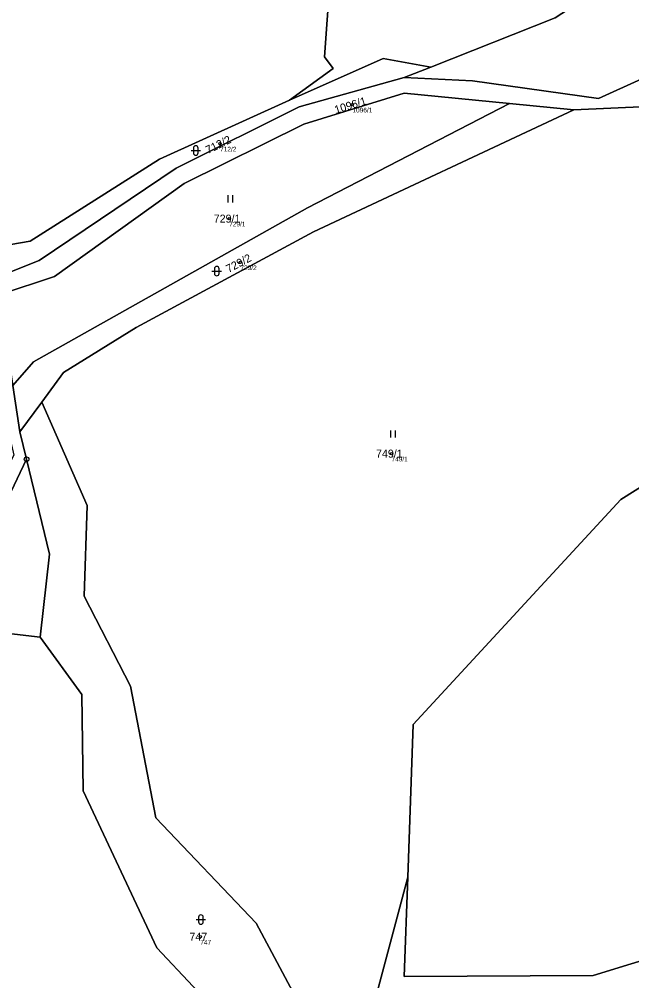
# Model space of a CAD drawing. Extents: x -554500 to -548272, y -1079733 to -1073730.
# Drawn here: x -552674.2 to -552544.1, y -1076720.4 to -1076516.2 of the extents above; entities that cross this region are included whole.
import ezdxf

# ---------------------------------------------------------------- set-up
doc = ezdxf.new("R2010")
doc.units = 0
for name, color, linetype in [('Definiční body', 7, 'Continuous'), ('Hranice parcel', 7, 'Continuous'), ('Parcelní čísla', 7, 'Continuous'), ('Polygon parcely', 7, 'Continuous'), ('Značky bodu BP', 7, 'Continuous'), ('Značky kultur', 7, 'Continuous')]:
    doc.layers.add(name, color=color, linetype=linetype)

msp = doc.modelspace()

# ---------------------------------------------------------------- linework, layer by layer
at = {"layer": 'Definiční body'}
for centre in [(-552603.42, -1076534.33994), (-552631.54, -1076542.62994), (-552629.61, -1076558.53994), (-552627.22, -1076567.79994), (-552595.12, -1076608.42994), (-552635.75, -1076711.01994)]:
    msp.add_circle(centre, 0.25, dxfattribs=at)
at = {"layer": 'Hranice parcel'}
for p, q in [((-552592.41, -1076528.61), (-552586.77, -1076526.37)), ((-552556.35, -1076535.43), (-552570.04, -1076534.1)), ((-552675.63, -1076593.95), (-552674.1, -1076603.82)), ((-552674.1, -1076603.82), (-552669.45, -1076597.48)), ((-552674.1, -1076603.82), (-552672.69, -1076609.64)), ((-552669.8, -1076647.4), (-552694.57, -1076644.52))]:
    msp.add_line(p, q, dxfattribs=at)
for points in [[(-552616.83, -1076533.42), (-552607.55, -1076526.7), (-552609.35, -1076524.22), (-552607.13, -1076493.71), (-552602.77, -1076462.46), (-552606.68, -1076454.87), (-552601.23, -1076431.08)], [(-552586.77, -1076526.37), (-552560.32, -1076515.93), (-552515.35, -1076486.6)], [(-552592.41, -1076528.61), (-552577.9, -1076529.28), (-552551.15, -1076533.06), (-552541.94, -1076528.83), (-552523.76, -1076530.08), (-552497.9, -1076522.82), (-552486.35, -1076519.2)], [(-552586.77, -1076526.37), (-552596.9, -1076524.56), (-552616.83, -1076533.42)], [(-552487.5, -1076524.06), (-552494.64, -1076526.4), (-552523.34, -1076533.93), (-552556.35, -1076535.43)], [(-552680.53, -1076571.59), (-552670.01, -1076567.43), (-552640.86, -1076547.83), (-552614.73, -1076534.83), (-552592.41, -1076528.61)], [(-552681.83, -1076565.04), (-552671.92, -1076563.36), (-552644.44, -1076545.91), (-552616.83, -1076533.42)], [(-552570.04, -1076534.1), (-552592.41, -1076531.92), (-552613.77, -1076538.47), (-552639.17, -1076551.08), (-552666.75, -1076570.81), (-552678.36, -1076574.64), (-552677.68, -1076580.73), (-552675.63, -1076593.95)], [(-552675.63, -1076593.95), (-552671.17, -1076588.94), (-552612.98, -1076556.28), (-552570.04, -1076534.1)], [(-552669.45, -1076597.48), (-552664.86, -1076591.22), (-552649.36, -1076581.64), (-552611.72, -1076561.31), (-552556.35, -1076535.43)], [(-552591.68, -1076698.35), (-552590.54, -1076665.97), (-552546.35, -1076618.16), (-552480.18, -1076576.63)], [(-552606.96, -1076782.38), (-552614.61, -1076740.01), (-552614.42, -1076725.85), (-552623.86, -1076708.12), (-552645.2, -1076685.73), (-552650.59, -1076657.78), (-552660.44, -1076638.73), (-552659.8, -1076619.44), (-552669.45, -1076597.48)], [(-552672.69, -1076609.64), (-552678.7, -1076622.12), (-552694.57, -1076644.52)], [(-552669.8, -1076647.4), (-552667.82, -1076629.78), (-552672.69, -1076609.64)], [(-552618.04, -1076776.84), (-552620.31, -1076767.74), (-552628.49, -1076753.02), (-552630.07, -1076741.43), (-552629.55, -1076729.8), (-552644.98, -1076713.39), (-552660.65, -1076680.06), (-552660.92, -1076659.58), (-552669.8, -1076647.4)], [(-552606.96, -1076782.38), (-552603.83, -1076744), (-552591.68, -1076698.35)], [(-552487.68, -1076699.44), (-552552.28, -1076719.26), (-552592.42, -1076719.43), (-552591.68, -1076698.35)]]:
    msp.add_lwpolyline(points, dxfattribs=at)
at = {"layer": 'Polygon parcely'}
for points in [[(-552518.46, -1076483.85), (-552483.61, -1076456.09), (-552448.47, -1076430.54), (-552457.53, -1076406.36), (-552525.71, -1076388.4), (-552593.59, -1076427.89), (-552601.23, -1076431.08), (-552606.68, -1076454.87), (-552602.77, -1076462.46), (-552607.13, -1076493.71), (-552609.35, -1076524.22), (-552607.55, -1076526.7), (-552616.83, -1076533.42), (-552596.9, -1076524.56), (-552586.77, -1076526.37), (-552560.32, -1076515.93), (-552515.35, -1076486.6)], [(-552671.92, -1076563.36), (-552644.44, -1076545.91), (-552616.83, -1076533.42), (-552607.55, -1076526.7), (-552609.35, -1076524.22), (-552607.13, -1076493.71), (-552602.77, -1076462.46), (-552606.68, -1076454.87), (-552601.23, -1076431.08), (-552610.94, -1076435.25), (-552618.03, -1076437.64), (-552701.4, -1076465.61), (-552701.24, -1076466.42), (-552698.36, -1076481.06), (-552684.08, -1076553.72), (-552681.41, -1076548.9), (-552679.88, -1076552.32), (-552683.15, -1076558.42), (-552681.83, -1076565.04)], [(-552497.9, -1076522.82), (-552486.35, -1076519.2), (-552480.24, -1076488.14), (-552495.5, -1076499.17), (-552515.35, -1076486.6), (-552560.32, -1076515.93), (-552586.77, -1076526.37), (-552592.41, -1076528.61), (-552577.9, -1076529.28), (-552551.15, -1076533.06), (-552541.94, -1076528.83), (-552523.76, -1076530.08)], [(-552670.01, -1076567.43), (-552640.86, -1076547.83), (-552614.73, -1076534.83), (-552592.41, -1076528.61), (-552586.77, -1076526.37), (-552596.9, -1076524.56), (-552616.83, -1076533.42), (-552644.44, -1076545.91), (-552671.92, -1076563.36), (-552681.83, -1076565.04), (-552680.53, -1076571.59)], [(-552487.5, -1076524.06), (-552494.64, -1076526.4), (-552523.34, -1076533.93), (-552556.35, -1076535.43), (-552611.72, -1076561.31), (-552649.36, -1076581.64), (-552664.86, -1076591.22), (-552669.45, -1076597.48), (-552659.8, -1076619.44), (-552660.44, -1076638.73), (-552650.59, -1076657.78), (-552645.2, -1076685.73), (-552623.86, -1076708.12), (-552614.42, -1076725.85), (-552614.61, -1076740.01), (-552606.96, -1076782.38), (-552603.83, -1076744), (-552591.68, -1076698.35), (-552590.54, -1076665.97), (-552546.35, -1076618.16), (-552480.18, -1076576.63), (-552490.19, -1076536.01)], [(-552666.75, -1076570.81), (-552678.36, -1076574.64), (-552677.68, -1076580.73), (-552675.63, -1076593.95), (-552671.17, -1076588.94), (-552612.98, -1076556.28), (-552570.04, -1076534.1), (-552592.41, -1076531.92), (-552613.77, -1076538.47), (-552639.17, -1076551.08)], [(-552570.04, -1076534.1), (-552612.98, -1076556.28), (-552671.17, -1076588.94), (-552675.63, -1076593.95), (-552674.1, -1076603.82), (-552669.45, -1076597.48), (-552664.86, -1076591.22), (-552649.36, -1076581.64), (-552611.72, -1076561.31), (-552556.35, -1076535.43)], [(-552442.82, -1076662.41), (-552388.41, -1076604.22), (-552360.56, -1076591.81), (-552353.27, -1076582.68), (-552346, -1076567.97), (-552349.96, -1076565.5), (-552371.43, -1076578.9), (-552438.38, -1076618.51), (-552465.61, -1076566.07), (-552480.18, -1076576.63), (-552546.35, -1076618.16), (-552590.54, -1076665.97), (-552591.68, -1076698.35), (-552592.42, -1076719.43), (-552552.28, -1076719.26), (-552487.68, -1076699.44)], [(-552672.69, -1076609.64), (-552667.82, -1076629.78), (-552669.8, -1076647.4), (-552660.92, -1076659.58), (-552660.65, -1076680.06), (-552644.98, -1076713.39), (-552629.55, -1076729.8), (-552630.07, -1076741.43), (-552628.49, -1076753.02), (-552620.31, -1076767.74), (-552618.04, -1076776.84), (-552615.91, -1076785.32), (-552606.96, -1076782.38), (-552614.61, -1076740.01), (-552614.42, -1076725.85), (-552623.86, -1076708.12), (-552645.2, -1076685.73), (-552650.59, -1076657.78), (-552660.44, -1076638.73), (-552659.8, -1076619.44), (-552669.45, -1076597.48), (-552674.1, -1076603.82)], [(-552678.7, -1076622.12), (-552694.57, -1076644.52), (-552669.8, -1076647.4), (-552667.82, -1076629.78), (-552672.69, -1076609.64)], [(-552720.84, -1076681.61), (-552742.22, -1076698.68), (-552802.53, -1076753.57), (-552807.44, -1076758.04), (-552798.41, -1076769.47), (-552782.64, -1076768.18), (-552770.99, -1076773.38), (-552771.17, -1076793.34), (-552745.32, -1076799.56), (-552709.01, -1076798.45), (-552688.06, -1076798.63), (-552669.87, -1076796.53), (-552643.31, -1076782.96), (-552618.04, -1076776.84), (-552620.31, -1076767.74), (-552628.49, -1076753.02), (-552630.07, -1076741.43), (-552629.55, -1076729.8), (-552644.98, -1076713.39), (-552660.65, -1076680.06), (-552660.92, -1076659.58), (-552669.8, -1076647.4), (-552694.57, -1076644.52)], [(-552569.87, -1076747.24), (-552516.94, -1076726.5), (-552517.95, -1076728.12), (-552505.51, -1076723.85), (-552495.63, -1076717.74), (-552501.02, -1076705.15), (-552487.68, -1076699.44), (-552552.28, -1076719.26), (-552592.42, -1076719.43), (-552591.68, -1076698.35), (-552603.83, -1076744), (-552606.96, -1076782.38), (-552576.31, -1076765.02)]]:
    msp.add_lwpolyline(points, close=True, dxfattribs=at)
for points in [[(-552541.94, -1076528.83), (-552551.15, -1076533.06), (-552577.9, -1076529.28), (-552592.41, -1076528.61), (-552614.73, -1076534.83), (-552640.86, -1076547.83), (-552670.01, -1076567.43), (-552680.53, -1076571.59), (-552685.39, -1076579.48), (-552685.11, -1076580.27), (-552675.9, -1076606.59), (-552675.36, -1076608.79), (-552682.82, -1076622.66), (-552699.48, -1076645.02), (-552725.91, -1076681.77), (-552747.09, -1076697.96), (-552755.28, -1076706.38), (-552807.25, -1076753.41)], [(-552802.53, -1076753.57), (-552742.22, -1076698.68), (-552720.84, -1076681.61), (-552694.57, -1076644.52), (-552678.7, -1076622.12), (-552672.69, -1076609.64), (-552674.1, -1076603.82), (-552675.63, -1076593.95), (-552677.68, -1076580.73), (-552678.36, -1076574.64), (-552666.75, -1076570.81), (-552639.17, -1076551.08), (-552613.77, -1076538.47), (-552592.41, -1076531.92), (-552570.04, -1076534.1), (-552556.35, -1076535.43), (-552523.34, -1076533.93)]]:
    msp.add_lwpolyline(points, dxfattribs=at)
at = {"layer": 'Značky bodu BP'}
for radius in [0.5, 0.0303]:
    msp.add_circle((-552672.69, -1076609.63988), radius, dxfattribs=at)
at = {"layer": 'Značky kultur'}
for p, q in [((-552637.231, -1076543.571), (-552637.231, -1076544.572)), ((-552636.229, -1076544.572), (-552636.229, -1076543.571)), ((-552637.731, -1076544.071), (-552635.729, -1076544.071)), ((-552629.841, -1076555.09), (-552629.841, -1076553.59)), ((-552628.84, -1076555.09), (-552628.84, -1076553.59)), ((-552633.271, -1076569.681), (-552631.269, -1076569.681)), ((-552632.771, -1076569.181), (-552632.771, -1076570.182)), ((-552631.769, -1076570.182), (-552631.769, -1076569.181)), ((-552595.291, -1076605.04), (-552595.291, -1076603.54)), ((-552594.29, -1076605.04), (-552594.29, -1076603.54)), ((-552636.131, -1076706.861), (-552636.131, -1076707.862)), ((-552635.129, -1076707.862), (-552635.129, -1076706.861)), ((-552636.631, -1076707.361), (-552634.629, -1076707.361))]:
    msp.add_line(p, q, dxfattribs=at)
for centre, start, end in [((-552636.73, -1076543.5709), 0, 180), ((-552636.73, -1076544.5709), 180, 359.9878861), ((-552632.27, -1076569.1809), 0, 180), ((-552632.27, -1076570.1809), 180, 359.9878861), ((-552635.63, -1076706.8609), 0, 180), ((-552635.63, -1076707.8609), 180, 359.9878861)]:
    msp.add_arc(centre, 0.5, start, end, dxfattribs=at)

# ---------------------------------------------------------------- texts
at = {"layer": 'Definiční body'}
for s, p in [('1096/1', (-552603.42, -1076535.996)), ('712/2', (-552631.54, -1076544.286)), ('729/1', (-552629.61, -1076560.196)), ('729/2', (-552627.22, -1076569.456)), ('749/1', (-552595.12, -1076610.086)), ('747', (-552635.75, -1076712.676))]:
    msp.add_text(s, height=0.999996, dxfattribs=at).set_placement(p)
at = {"layer": 'Parcelní čísla'}
for s, rotation, p in [('1096/1', 17, (-552606.946, -1076536.307)), ('712/2', 26, (-552634.132, -1076544.839)), ('729/2', 28, (-552629.733, -1076570.099))]:
    msp.add_text(s, height=1.699998, rotation=rotation, dxfattribs=at).set_placement(p)
for s, p in [('729/1', (-552632.908, -1076559.39)), ('749/1', (-552598.418, -1076609.28)), ('747', (-552638.075, -1076711.87))]:
    msp.add_text(s, height=1.699998, dxfattribs=at).set_placement(p)

doc.saveas('drawing.dxf')
